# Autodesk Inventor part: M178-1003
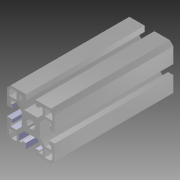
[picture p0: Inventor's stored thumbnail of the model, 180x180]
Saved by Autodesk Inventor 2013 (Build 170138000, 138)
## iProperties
Created: 2004-10
Material: Aluminium - 6061
Document SubType Name: Modeling
Designer: Autodesk, Inc.
Manufacturer: Standard
Standards Organization: Custom
Description: TABLE, SUPPORT BAR, SIDE
Stock Number: 10-040
Catalog Web Link: http://www.parker.com/ead/cm1.asp?cmid=809
Vendor: PARKER IPS
Part Number: M178-1003
Mass: 179.948 g
Surface Area: 483.565 cm^2
Volume: 66.4013 cm^3
Density: 2.71 g/cm^3
CAGE: 1LJX3
Dept. ID: Product Design
Description #2: ---
Finish #1: ---
Finish #2: ---
Material ID: ---
Project Number: ---
Length: 682.000 mm
Author: Autodesk, Inc.
Revision Number: A
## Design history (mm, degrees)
derived "40 Series Profiles.ipt"
feature "IPS40SeriesCutout2"
mirror "Mirror1"
body "Solid1"
tag "TaggingFeature2"
sketch "Sketch4"
  geometry: L1 (354.5, -56.5)-(354.5, -35.5) reference; L2 (-327.5, -35.5)-(354.5, -35.5) reference; L3 (354.5, -43.5)-(-327.5, -43.5) reference; L4 (334.5, -35.5)-(334.5, -43.5); C1 r 10 at (334.5, -39.5)
  constraints: 2 end point, 2 point on line, 1 centre point, 1 midpoint, 1 perpendicular
  dimensions: "d6" = 20 distance between parallel lines of L4 L1; "d7" = 20 diameter of C1
feature "Solid1::40 Series Profiles.ipt" dims "ScaleForDerivedMember" = 10
other parameters: "Length" = 682
